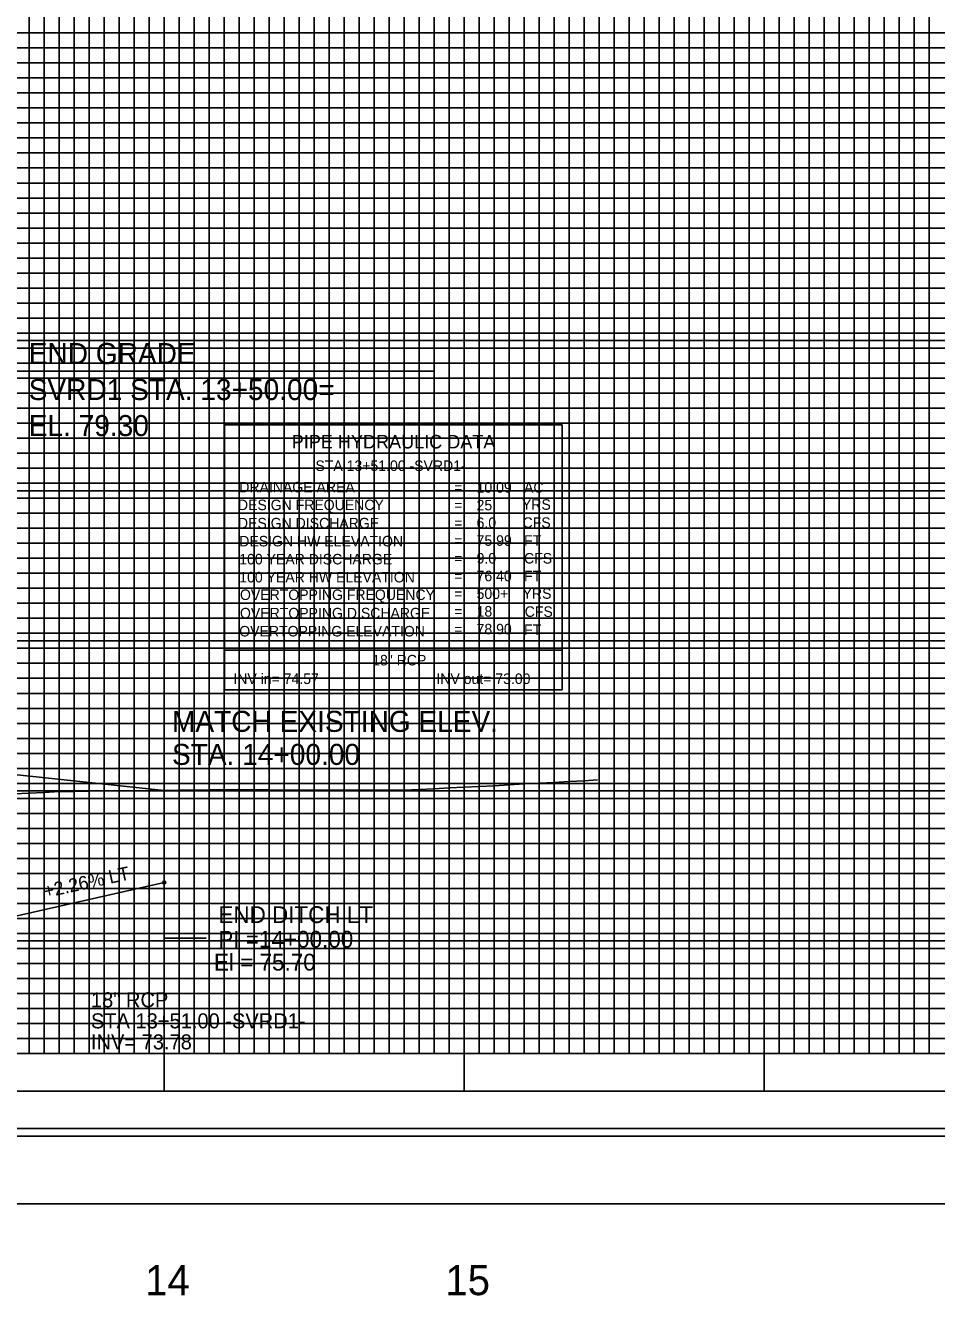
# Model space of a CAD drawing. Extents: x 2345490 to 2436403, y 465165 to 573888.
# Drawn here: x 2382120.5 to 2382424.3, y 510373.8 to 510796.9 of the extents above; entities that cross this region are included whole.
import ezdxf

# ---------------------------------------------------------------- set-up
doc = ezdxf.new("R2010")
doc.units = 0
for name, color, linetype in [('Old_Level_1', 7, 'Continuous'), ('Old_Level_18', 7, 'Continuous'), ('Old_Level_2', 7, 'Continuous'), ('Old_Level_3', 7, 'Continuous'), ('Old_Level_4', 7, 'Continuous'), ('Old_Level_41', 7, 'Continuous'), ('Old_Level_42', 7, 'Continuous'), ('Old_Level_43', 7, 'Continuous'), ('Old_Level_50', 7, 'Continuous'), ('Old_Level_51', 7, 'Continuous'), ('Old_Level_57', 7, 'Continuous'), ('Old_Level_62', 7, 'Continuous'), ('Old_Level_63', 7, 'Continuous'), ('Prop Vertical Profile Grade', 7, 'Continuous')]:
    doc.layers.add(name, color=color, linetype=linetype)

msp = doc.modelspace()

# ---------------------------------------------------------------- linework, layer by layer
at = {"layer": 'Old_Level_1'}
for points in [[(2382116.799, 510540.9192), (2382121.799, 510541.16197), (2382126.799, 510541.40475), (2382131.799, 510541.62891), (2382136.799, 510541.70164), (2382141.799, 510541.7801), (2382146.799, 510541.85856), (2382151.799, 510541.93702), (2382156.799, 510541.9021), (2382161.799, 510541.96441), (2382166.799, 510542.02672), (2382171.799, 510542.08903), (2382176.799, 510542.15134), (2382181.799, 510542.21365), (2382186.799, 510542.23698), (2382191.799, 510542.22935), (2382196.799, 510542.21246), (2382201.799, 510542.19557), (2382206.799, 510542.17868), (2382211.799, 510542.16179), (2382216.799, 510542.17076), (2382221.799, 510542.15733), (2382226.799, 510542.13796), (2382231.799, 510542.11859), (2382236.799, 510542.09921), (2382241.799, 510542.07984), (2382246.799, 510542.16869), (2382251.799, 510542.36239), (2382256.799, 510542.61497), (2382261.799, 510542.86756), (2382266.799, 510543.12014)], [(2382266.799, 510543.12014), (2382271.799, 510543.37272), (2382276.799, 510543.6253), (2382281.799, 510543.93991), (2382286.799, 510544.19651), (2382291.799, 510544.4531), (2382296.799, 510544.7097), (2382301.799, 510544.96629), (2382306.799, 510545.22289), (2382311.249, 510545.51562)]]:
    msp.add_lwpolyline(points, dxfattribs=at)
at = {"layer": 'Old_Level_18'}
msp.add_lwpolyline([(2383216.79875, 511479.3835), (2381716.79875, 511479.3835), (2381716.79875, 510429.3835), (2383216.79875, 510429.3835)], close=True, dxfattribs=at)
at = {"layer": 'Old_Level_2'}
msp.add_line((2382116.799, 510681.70631), (2382256.61089, 510681.70631), dxfattribs=at)
at = {"layer": 'Old_Level_3'}
for p, q in [((2382166.799, 510559.38264), (2382295.1361, 510559.38264)), ((2382166.799, 510559.38264), (2382166.799, 510542.02672)), ((2382116.799, 510500.0835), (2382166.799, 510511.3835)), ((2382166.799, 510492.79497), (2382166.799, 510511.3835)), ((2382180.84648, 510492.79497), (2382166.799, 510492.79497))]:
    msp.add_line(p, q, dxfattribs=at)
msp.add_circle((2382166.799, 510511.3835), 0.5, dxfattribs=at)
at = {"layer": 'Old_Level_4'}
for p, q in [((2382186.93805, 510663.78249), (2382299.43805, 510663.78249)), ((2382186.93805, 510588.78249), (2382186.93805, 510663.78249)), ((2382299.43805, 510663.78249), (2382299.43805, 510588.78249)), ((2382299.43805, 510588.78249), (2382186.93805, 510588.78249))]:
    msp.add_line(p, q, dxfattribs=at)
msp.add_lwpolyline([(2382186.93805, 510588.78249), (2382299.43805, 510588.78249), (2382299.43805, 510575.56749), (2382186.93805, 510575.56749)], close=True, dxfattribs=at)
at = {"layer": 'Old_Level_41'}
msp.add_line((2383216.79875, 510454.3835), (2381716.79875, 510454.3835), dxfattribs=at)
for points in [[(2382141.79875, 511479.3835), (2382141.79875, 510454.3835), (2382191.79875, 510454.3835), (2382191.79875, 511479.3835)], [(2382166.79875, 511479.3835), (2382166.79875, 510454.3835), (2382216.79875, 510454.3835), (2382216.79875, 511479.3835)], [(2382241.79875, 511479.3835), (2382241.79875, 510454.3835), (2382291.79875, 510454.3835), (2382291.79875, 511479.3835)], [(2382266.79875, 511479.3835), (2382266.79875, 510454.3835), (2382316.79875, 510454.3835), (2382316.79875, 511479.3835)], [(2382341.79875, 511479.3835), (2382341.79875, 510454.3835), (2382391.79875, 510454.3835), (2382391.79875, 511479.3835)], [(2382366.79875, 511479.3835), (2382366.79875, 510454.3835), (2382416.79875, 510454.3835), (2382416.79875, 511479.3835)], [(2383216.79875, 510779.3835), (2381716.79875, 510779.3835), (2381716.79875, 510729.3835), (2383216.79875, 510729.3835)], [(2383216.79875, 510704.3835), (2381716.79875, 510704.3835), (2381716.79875, 510754.3835), (2383216.79875, 510754.3835)], [(2383216.79875, 510679.3835), (2381716.79875, 510679.3835), (2381716.79875, 510629.3835), (2383216.79875, 510629.3835)], [(2383216.79875, 510579.3835), (2381716.79875, 510579.3835), (2381716.79875, 510529.3835), (2383216.79875, 510529.3835)], [(2383216.79875, 510504.3835), (2381716.79875, 510504.3835), (2381716.79875, 510554.3835), (2383216.79875, 510554.3835)], [(2383216.79875, 510479.3835), (2381716.79875, 510479.3835)]]:
    msp.add_lwpolyline(points, dxfattribs=at)
at = {"layer": 'Old_Level_42'}
msp.add_lwpolyline([(2383216.79875, 510604.3835), (2381716.79875, 510604.3835), (2381716.79875, 510654.3835), (2383216.79875, 510654.3835)], dxfattribs=at)
at = {"layer": 'Old_Level_43'}
for points in [[(2382121.79875, 511479.3835), (2382121.79875, 510454.3835), (2382126.79875, 510454.3835), (2382126.79875, 511479.3835)], [(2382131.79875, 511479.3835), (2382131.79875, 510454.3835), (2382136.79875, 510454.3835), (2382136.79875, 511479.3835)], [(2382146.79875, 511479.3835), (2382146.79875, 510454.3835), (2382151.79875, 510454.3835), (2382151.79875, 511479.3835)], [(2382156.79875, 511479.3835), (2382156.79875, 510454.3835), (2382161.79875, 510454.3835), (2382161.79875, 511479.3835)], [(2382171.79875, 511479.3835), (2382171.79875, 510454.3835), (2382176.79875, 510454.3835), (2382176.79875, 511479.3835)], [(2382181.79875, 511479.3835), (2382181.79875, 510454.3835), (2382186.79875, 510454.3835), (2382186.79875, 511479.3835)], [(2382196.79875, 511479.3835), (2382196.79875, 510454.3835), (2382201.79875, 510454.3835), (2382201.79875, 511479.3835)], [(2382206.79875, 511479.3835), (2382206.79875, 510454.3835), (2382211.79875, 510454.3835), (2382211.79875, 511479.3835)], [(2382221.79875, 511479.3835), (2382221.79875, 510454.3835), (2382226.79875, 510454.3835), (2382226.79875, 511479.3835)], [(2382231.79875, 511479.3835), (2382231.79875, 510454.3835), (2382236.79875, 510454.3835), (2382236.79875, 511479.3835)], [(2382246.79875, 511479.3835), (2382246.79875, 510454.3835)], [(2382251.79875, 511479.3835), (2382251.79875, 510454.3835), (2382256.79875, 510454.3835), (2382256.79875, 511479.3835), (2382261.79875, 511479.3835), (2382261.79875, 510454.3835), (2382271.79875, 510454.3835), (2382271.79875, 511479.3835), (2382276.79875, 511479.3835), (2382276.79875, 510454.3835), (2382281.79875, 510454.3835), (2382281.79875, 511479.3835), (2382286.79875, 511479.3835), (2382286.79875, 510454.3835)], [(2382296.79875, 510454.3835), (2382296.79875, 511479.3835)], [(2382301.79875, 511479.3835), (2382301.79875, 510454.3835), (2382306.79875, 510454.3835), (2382306.79875, 511479.3835)], [(2382311.79875, 511479.3835), (2382311.79875, 510454.3835), (2382321.79875, 510454.3835), (2382321.79875, 511479.3835)], [(2382326.79875, 511479.3835), (2382326.79875, 510454.3835), (2382326.79875, 510454.3835), (2382331.79875, 510454.3835), (2382331.79875, 511479.3835)], [(2382336.79875, 511479.3835), (2382336.79875, 510454.3835), (2382346.79875, 510454.3835), (2382346.79875, 511479.3835)], [(2382351.79875, 511479.3835), (2382351.79875, 510454.3835), (2382356.79875, 510454.3835), (2382356.79875, 511479.3835)], [(2382361.79875, 511479.3835), (2382361.79875, 510454.3835), (2382371.79875, 510454.3835), (2382371.79875, 511479.3835)], [(2382376.79875, 511479.3835), (2382376.79875, 510454.3835), (2382381.79875, 510454.3835), (2382381.79875, 511479.3835)], [(2382386.79875, 511479.3835), (2382386.79875, 510454.3835), (2382396.79875, 510454.3835), (2382396.79875, 511479.3835)], [(2382401.79875, 511479.3835), (2382401.79875, 510454.3835), (2382406.79875, 510454.3835), (2382406.79875, 511479.3835)], [(2382411.79875, 511479.3835), (2382411.79875, 510454.3835), (2382421.79875, 510454.3835), (2382421.79875, 511479.3835)], [(2383166.79875, 510794.3835), (2381766.79875, 510794.3835), (2381766.79875, 510789.3835), (2383166.79875, 510789.3835)], [(2383166.79875, 510784.3835), (2381766.79875, 510784.3835), (2381766.79875, 510774.3835), (2383166.79875, 510774.3835)], [(2383166.79875, 510769.3835), (2381766.79875, 510769.3835), (2381766.79875, 510764.3835), (2383166.79875, 510764.3835)], [(2383166.79875, 510759.3835), (2381766.79875, 510759.3835), (2381766.79875, 510749.3835), (2383166.79875, 510749.3835)], [(2383166.79875, 510744.3835), (2381766.79875, 510744.3835), (2381766.79875, 510739.3835), (2383166.79875, 510739.3835)], [(2383166.79875, 510734.3835), (2381766.79875, 510734.3835), (2381766.79875, 510724.3835), (2383166.79875, 510724.3835)], [(2383166.79875, 510719.3835), (2381766.79875, 510719.3835), (2381766.79875, 510714.3835), (2383166.79875, 510714.3835)], [(2383166.79875, 510709.3835), (2381766.79875, 510709.3835), (2381766.79875, 510699.3835), (2383166.79875, 510699.3835)], [(2383166.79875, 510694.3835), (2381766.79875, 510694.3835), (2381766.79875, 510689.3835), (2383166.79875, 510689.3835)], [(2383166.79875, 510684.3835), (2381766.79875, 510684.3835), (2381766.79875, 510674.3835), (2383166.79875, 510674.3835)], [(2383166.79875, 510669.3835), (2381766.79875, 510669.3835), (2381766.79875, 510664.3835), (2383166.79875, 510664.3835)], [(2383166.79875, 510659.3835), (2381766.79875, 510659.3835)], [(2381766.79875, 510649.3835), (2383166.79875, 510649.3835)], [(2383166.79875, 510644.3835), (2381766.79875, 510644.3835), (2381766.79875, 510639.3835), (2383166.79875, 510639.3835)], [(2383166.79875, 510634.3835), (2381766.79875, 510634.3835)], [(2381766.79875, 510624.3835), (2383166.79875, 510624.3835)], [(2383166.79875, 510619.3835), (2381766.79875, 510619.3835), (2381766.79875, 510614.3835), (2383166.79875, 510614.3835)], [(2383166.79875, 510609.3835), (2381766.79875, 510609.3835), (2381766.79875, 510599.3835), (2383166.79875, 510599.3835)], [(2383166.79875, 510594.3835), (2381766.79875, 510594.3835), (2381766.79875, 510589.3835), (2383166.79875, 510589.3835)], [(2383166.79875, 510584.3835), (2381766.79875, 510584.3835), (2381766.79875, 510574.3835), (2383166.79875, 510574.3835)], [(2383166.79875, 510569.3835), (2381766.79875, 510569.3835), (2381766.79875, 510564.3835), (2383166.79875, 510564.3835)], [(2383166.79875, 510559.3835), (2381766.79875, 510559.3835), (2381766.79875, 510549.3835), (2383166.79875, 510549.3835)], [(2383166.79875, 510544.3835), (2381766.79875, 510544.3835), (2381766.79875, 510539.3835), (2383166.79875, 510539.3835)], [(2383166.79875, 510534.3835), (2381766.79875, 510534.3835), (2381766.79875, 510524.3835), (2383166.79875, 510524.3835)], [(2383166.79875, 510519.3835), (2381766.79875, 510519.3835), (2381766.79875, 510514.3835), (2383166.79875, 510514.3835)], [(2383166.79875, 510509.3835), (2381766.79875, 510509.3835), (2381766.79875, 510499.3835), (2383166.79875, 510499.3835)], [(2383166.79875, 510494.3835), (2381766.79875, 510494.3835), (2381766.79875, 510489.3835), (2383166.79875, 510489.3835)], [(2383166.79875, 510484.3835), (2381766.79875, 510484.3835), (2381766.79875, 510474.3835), (2383166.79875, 510474.3835)], [(2383166.79875, 510469.3835), (2381766.79875, 510469.3835), (2381766.79875, 510464.3835), (2383166.79875, 510464.3835)], [(2383166.79875, 510459.3835), (2381766.79875, 510459.3835)]]:
    msp.add_lwpolyline(points, dxfattribs=at)
at = {"layer": 'Old_Level_50'}
msp.add_lwpolyline([(2383229.29875, 511481.9335), (2381562.79875, 511481.9335), (2381562.79875, 510426.8335), (2383229.29875, 510426.8335)], close=True, dxfattribs=at)
at = {"layer": 'Old_Level_51'}
msp.add_lwpolyline([(2383233.79875, 511504.3835), (2381549.79875, 511504.3835), (2381549.79875, 510404.3835), (2383233.79875, 510404.3835)], close=True, dxfattribs=at)
at = {"layer": 'Old_Level_57'}
for p, q in [((2381716.79925, 510691.88375), (2383066.79875, 510691.88375)), ((2382166.79875, 510441.88375), (2382166.79875, 510691.88375)), ((2382166.79875, 510441.98375), (2382166.79875, 510691.88375)), ((2382266.79875, 510441.88375), (2382266.79875, 510691.88375)), ((2382266.79875, 510441.98375), (2382266.79875, 510691.88375)), ((2382366.79875, 510441.88375), (2382366.79875, 510691.88375)), ((2382366.79875, 510441.98375), (2382366.79875, 510691.88375)), ((2381716.79925, 510641.88375), (2383066.79875, 510641.88375)), ((2381716.79925, 510591.88375), (2383066.79875, 510591.88375)), ((2381716.79925, 510541.88375), (2383066.79875, 510541.88375)), ((2381716.799, 510491.88375), (2383066.79875, 510491.88375)), ((2381716.79925, 510441.88375), (2383066.79875, 510441.88375))]:
    msp.add_line(p, q, dxfattribs=at)
at = {"layer": 'Old_Level_63'}
msp.add_line((2381766.799, 510404.3835), (2382366.799, 510404.3835), dxfattribs=at)
at = {"layer": 'Prop Vertical Profile Grade'}
msp.add_line((2382166.799, 510542.02672), (2382116.799, 510547.3835), dxfattribs=at)

# ---------------------------------------------------------------- texts
at = {"layer": 'Old_Level_2'}
for s, height, p in [('END GRADE', 7.000001, (2382121.63483, 510684.07806)), ('SVRD1 STA. 13+50.00=', 7.0000005, (2382121.63483, 510672.07805)), ('EL. 79.30', 7.000001, (2382121.63483, 510660.07805)), ('MATCH EXISTING ELEV.', 7.0000005, (2382169.39579, 510561.54225)), ('STA. 14+00.00', 7.0000005, (2382169.39579, 510550.54225))]:
    msp.add_text(s, height=height, dxfattribs=at).set_placement(p)
at = {"layer": 'Old_Level_3'}
for s, height, rotation, p in [('+2.26% LT', 4.48, 12.412707, (2382127.15492, 510506.17169)), ('END DITCH LT', 5.6000004, 360, (2382184.858, 510497.86285)), ('PI =14+00.00', 5.6000004, 360, (2382184.858, 510489.66817)), ('El = 75.70', 5.6, 360, (2382183.39415, 510482.03924))]:
    msp.add_text(s, height=height, rotation=rotation, dxfattribs=at).set_placement(p)
for s, height, p in [('18" RCP', 4.999999, (2382142.39029, 510469.78413)), ('STA 13+51.00 -SVRD1-', 4.9999995, (2382142.39029, 510462.78413)), ('INV= 73.78', 4.999999, (2382142.39029, 510455.78413))]:
    msp.add_text(s, height=height, dxfattribs=at).set_placement(p)
at = {"layer": 'Old_Level_4'}
for s, height, p in [('PIPE HYDRAULIC DATA', 4.49985, (2382209.33805, 510655.95749)), ('STA 13+51.00 -SVRD1-', 3.4998, (2382217.2318, 510648.45724)), ('DRAINAGE AREA', 3.49995, (2382191.83805, 510641.33249)), ('10.09', 3.49995, (2382270.94855, 510641.23204)), ('AC', 3.49995, (2382286.76305, 510641.23249)), ('=        ', 3.49995, (2382263.48805, 510641.23249)), ('DESIGN FREQUENCY', 3.49995, (2382191.38805, 510635.40749)), ('=        ', 3.49995, (2382263.48805, 510635.33249)), ('25', 3.49995, (2382270.94855, 510635.33209)), ('YRS', 3.49995, (2382286.06305, 510635.53249)), ('DESIGN DISCHARGE', 3.49995, (2382191.38805, 510629.33249)), ('6.0', 3.49995, (2382270.94855, 510629.43214)), ('CFS', 3.49995, (2382286.28805, 510629.50749)), ('=        ', 3.49995, (2382263.48805, 510629.43249)), ('DESIGN HW ELEVATION', 3.49995, (2382191.83805, 510623.33249)), ('=        ', 3.49995, (2382263.48805, 510623.53249)), ('75.99', 3.49995, (2382270.94855, 510623.53219)), ('FT', 3.49995, (2382286.76305, 510623.53249)), ('100 YEAR DISCHARGE', 3.49995, (2382191.83805, 510617.33249)), ('=        ', 3.49995, (2382263.48805, 510617.63249)), ('9.0', 3.49995, (2382270.94855, 510617.63224)), ('CFS', 3.49995, (2382286.76305, 510617.63249)), ('76.40', 3.49995, (2382270.94855, 510611.73229)), ('FT', 3.49995, (2382286.76305, 510611.73249)), ('100 YEAR HW ELEVATION', 3.49995, (2382191.83805, 510611.33249)), ('=        ', 3.49995, (2382263.48805, 510611.73249)), ('OVERTOPPING FREQUENCY', 3.49995, (2382192.06305, 510605.48249)), ('=        ', 3.49995, (2382263.48805, 510605.83249)), ('500+', 3.49995, (2382270.94855, 510605.83234)), ('YRS', 3.49995, (2382286.28805, 510605.88249)), ('OVERTOPPING DISCHARGE', 3.49995, (2382192.06305, 510599.35749)), ('=        ', 3.49995, (2382263.48805, 510599.93249)), ('18', 3.49995, (2382270.94855, 510599.93239)), ('CFS', 3.49995, (2382286.98805, 510599.85749)), ('OVERTOPPING ELEVATION', 3.49995, (2382191.83805, 510593.33249)), ('=        ', 3.49995, (2382263.48805, 510594.03249)), ('78.90', 3.49995, (2382270.94855, 510594.03244)), ('FT', 3.49995, (2382286.76305, 510593.83249)), ('18" RCP', 3.4998, (2382236.1438, 510583.68024)), ('INV in= 74.57', 3.4998, (2382189.87055, 510577.49449)), ('INV out= 73.00', 3.4998, (2382257.5473, 510577.49449))]:
    msp.add_text(s, height=height, dxfattribs=at).set_placement(p)
at = {"layer": 'Old_Level_62'}
for s, p in [('14', (2382160.44748, 510373.90358)), ('15', (2382260.53991, 510373.90358))]:
    msp.add_text(s, height=10, dxfattribs=at).set_placement(p)

doc.saveas('drawing.dxf')
